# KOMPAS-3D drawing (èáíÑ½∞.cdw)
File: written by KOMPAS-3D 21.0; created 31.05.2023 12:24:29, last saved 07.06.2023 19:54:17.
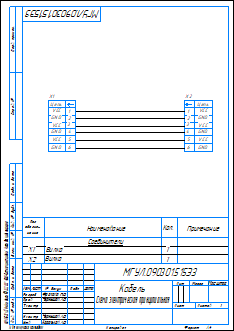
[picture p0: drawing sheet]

Sheet 1: A4, portrait

Document properties: Полное имя файла: C:\Artanis\Учеба\Чертежи\Кабель.cdw

Title block, sheet 1: Наименование: Кабель / Схема электрическая принципиальная; designation: МГУЛ.090301.515ЭЗ; Количество листов документа: 1; Форматы листов документа: A4; stored path: C:\Artanis\Учеба\Чертежи\Основной.cdw; Разработал: Фролова П.В.; Проверил: Чернышов А.В.; Н. контр.: Чернышов А.В.; Утвердил: Корольков А.В.

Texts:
  Цепь
  GND
  VCC
  Поз.
  обозна-
  чение
  Соединители
  Кол.
  Вилка
  Стили документа
Dimensions and other numbers on the sheet: 1; 2; 3; 4; 5; 6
